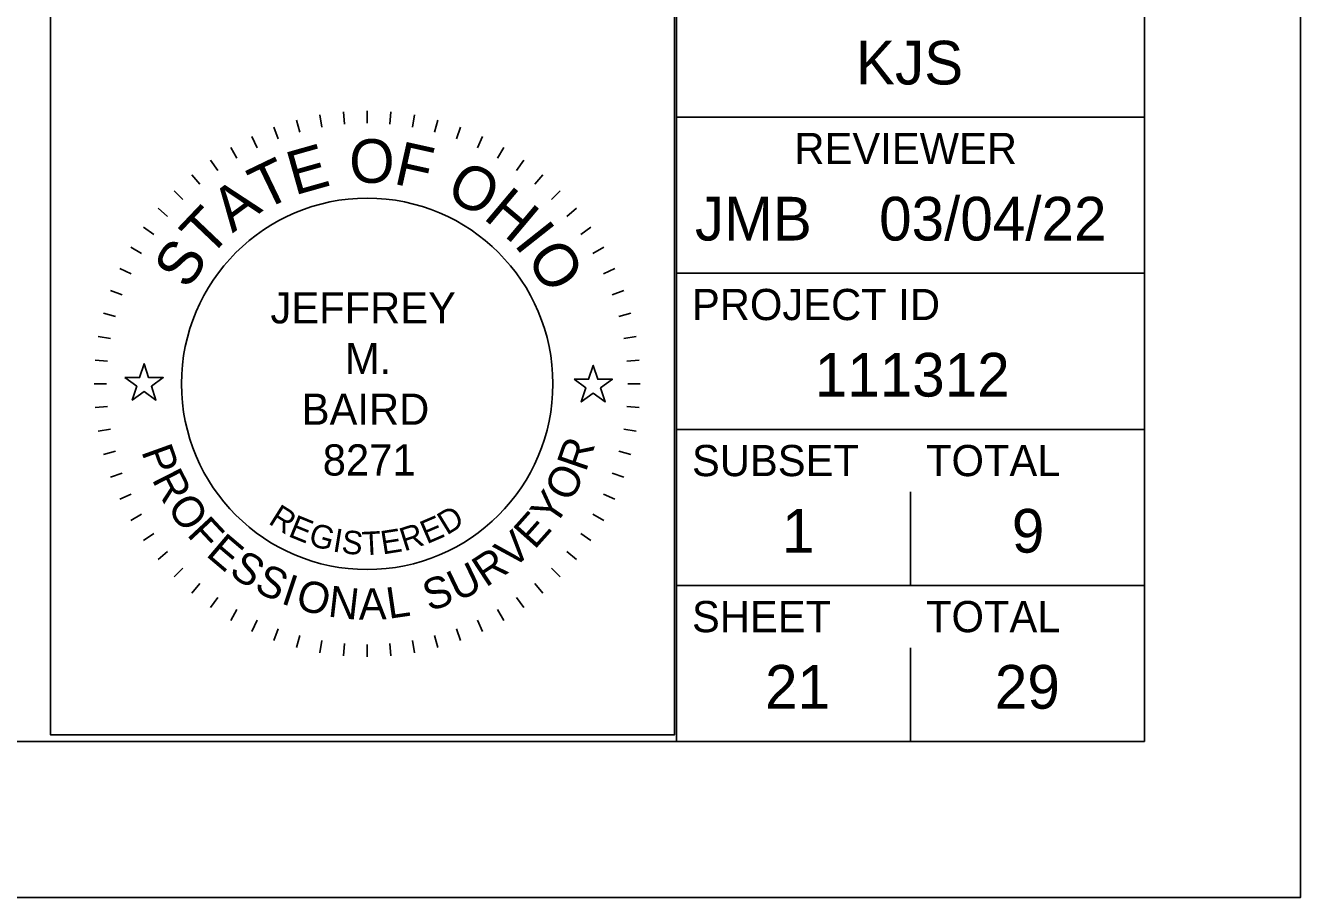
# Model space of a CAD drawing. Extents: x 0 to 104, y 0 to 37.
# Drawn here: x 29.914 to 34, y 0 to 2.794 of the extents above; entities that cross this region are included whole.
import ezdxf

# ---------------------------------------------------------------- set-up
doc = ezdxf.new("R2010")
doc.units = 0
for name, color, linetype in [('SC_Scratch3', 7, 'Continuous'), ('SH_Cut_Line', 7, 'Continuous'), ('SH_Data', 7, 'Continuous'), ('SH_Named_Boundary', 7, 'Continuous')]:
    doc.layers.add(name, color=color, linetype=linetype)

msp = doc.modelspace()

# ---------------------------------------------------------------- linework, layer by layer
at = {"layer": 'SC_Scratch3'}
msp.add_lwpolyline([(0, 0), (34, 0), (34, 22), (0, 22)], close=True, dxfattribs=at)
at = {"layer": 'SH_Cut_Line'}
for p, q in [((30.8574, 2.5074), (30.8644, 2.468)), ((30.9331, 2.5174), (30.9366, 2.4776)), ((31.0094, 2.5207), (31.0094, 2.4807)), ((31.0856, 2.5174), (31.0822, 2.4776)), ((31.1613, 2.5074), (31.1544, 2.468)), ((30.7101, 2.468), (30.7238, 2.4304)), ((30.7829, 2.4909), (30.7933, 2.4523)), ((31.2358, 2.4909), (31.2255, 2.4523)), ((31.3086, 2.468), (31.295, 2.4304)), ((30.6396, 2.4388), (30.6565, 2.4025)), ((31.3792, 2.4388), (31.3623, 2.4025)), ((30.5719, 2.4035), (30.5919, 2.3689)), ((31.4469, 2.4035), (31.4269, 2.3689)), ((30.5075, 2.3625), (30.5304, 2.3297)), ((31.5113, 2.3625), (31.4883, 2.3297)), ((30.4469, 2.316), (30.4727, 2.2854)), ((31.5718, 2.316), (31.5461, 2.2854)), ((30.3907, 2.2645), (30.4189, 2.2362)), ((31.6281, 2.2645), (31.5998, 2.2362)), ((30.3391, 2.2082), (30.3697, 2.1825)), ((31.6797, 2.2082), (31.649, 2.1825)), ((30.2926, 2.1476), (30.3254, 2.1247)), ((31.7261, 2.1476), (31.6934, 2.1247)), ((30.2516, 2.0832), (30.2863, 2.0632)), ((31.7672, 2.0832), (31.7325, 2.0632)), ((30.2164, 2.0155), (30.2526, 1.9986)), ((31.8024, 2.0155), (31.7661, 1.9986)), ((30.1872, 1.945), (30.2247, 1.9313)), ((31.8316, 1.945), (31.794, 1.9313)), ((30.1642, 1.8722), (30.2028, 1.8618)), ((31.8546, 1.8722), (31.8159, 1.8618)), ((30.1477, 1.7977), (30.1871, 1.7907)), ((31.8711, 1.7977), (31.8317, 1.7907)), ((30.1377, 1.722), (30.1776, 1.7185)), ((31.8811, 1.722), (31.8412, 1.7185)), ((30.1344, 1.6457), (30.1744, 1.6457)), ((31.8844, 1.6457), (31.8444, 1.6457)), ((30.1377, 1.5695), (30.1776, 1.573)), ((31.8811, 1.5695), (31.8412, 1.573)), ((30.1477, 1.4938), (30.1871, 1.5007)), ((31.8711, 1.4938), (31.8317, 1.5007)), ((30.1642, 1.4193), (30.2028, 1.4296)), ((31.8546, 1.4193), (31.8159, 1.4296)), ((30.1872, 1.3465), (30.2247, 1.3601)), ((31.8316, 1.3465), (31.794, 1.3601)), ((30.2164, 1.2759), (30.2526, 1.2928)), ((31.8024, 1.2759), (31.7661, 1.2928)), ((32.75, 1), (32.75, 1.3)), ((30.2516, 1.2082), (30.2863, 1.2282)), ((31.7672, 1.2082), (31.7325, 1.2282)), ((30.2926, 1.1439), (30.3254, 1.1668)), ((31.7261, 1.1439), (31.6934, 1.1668)), ((30.3391, 1.0833), (30.3697, 1.109)), ((31.6797, 1.0833), (31.649, 1.109)), ((30.3907, 1.027), (30.4189, 1.0553)), ((31.6281, 1.027), (31.5998, 1.0553)), ((30.4469, 0.9754), (30.4727, 1.0061)), ((31.5718, 0.9754), (31.5461, 1.0061)), ((30.5075, 0.929), (30.5304, 0.9617)), ((31.5113, 0.929), (31.4883, 0.9617)), ((30.5719, 0.888), (30.5919, 0.9226)), ((31.4469, 0.888), (31.4269, 0.9226)), ((30.6396, 0.8527), (30.6565, 0.889)), ((30.7101, 0.8235), (30.7238, 0.8611)), ((31.3086, 0.8235), (31.295, 0.8611)), ((31.3792, 0.8527), (31.3623, 0.889)), ((30.7829, 0.8005), (30.7933, 0.8392)), ((30.8574, 0.784), (30.8644, 0.8234)), ((31.1613, 0.784), (31.1544, 0.8234)), ((31.2358, 0.8005), (31.2255, 0.8392)), ((30.9331, 0.7741), (30.9366, 0.8139)), ((31.0094, 0.7707), (31.0094, 0.8107)), ((31.0856, 0.7741), (31.0822, 0.8139)), ((32.75, 0.5), (32.75, 0.8)), ((32.375, 0.675), (32.375, 0.675))]:
    msp.add_line(p, q, dxfattribs=at)
for points in [[(30.233, 1.6657), (30.2799, 1.6657), (30.2944, 1.7103), (30.3089, 1.6657), (30.3558, 1.6657), (30.3179, 1.6381), (30.3324, 1.5935), (30.2944, 1.6211), (30.2564, 1.5935), (30.2709, 1.6381)], [(31.6721, 1.6603), (31.719, 1.6603), (31.7335, 1.7049), (31.748, 1.6603), (31.7949, 1.6603), (31.757, 1.6327), (31.7715, 1.5881), (31.7335, 1.6157), (31.6955, 1.5881), (31.71, 1.6327)]]:
    msp.add_lwpolyline(points, close=True, dxfattribs=at)
msp.add_circle((31.0094, 1.6457), 0.595, dxfattribs=at)
at = {"layer": 'SH_Data'}
msp.add_lwpolyline([(29.9944, 3.1213), (31.9944, 3.1213), (31.9944, 0.5213), (29.9944, 0.5213)], close=True, dxfattribs=at)
at = {"layer": 'SH_Named_Boundary'}
for p, q in [((32, 0.5), (32, 21.5)), ((32, 2.5), (33.5, 2.5)), ((32, 2), (33.5, 2)), ((32, 1.5), (33.5, 1.5)), ((32, 1), (33.5, 1))]:
    msp.add_line(p, q, dxfattribs=at)
msp.add_lwpolyline([(1.5, 21.5), (33.5, 21.5), (33.5, 0.5), (1.5, 0.5)], close=True, dxfattribs=at)

# ---------------------------------------------------------------- texts
at = {"layer": 'SH_Cut_Line'}
for s, height, p in [('KJS', 0.14, (32.5757, 2.605)), ('REVIEWER', 0.1, (32.3783, 2.35)), ('03/04/22', 0.14, (32.6497, 2.105)), ('JMB', 0.14, (32.0596, 2.105)), ('JEFFREY', 0.1, (30.6993, 1.8395)), ('PROJECT ID', 0.1, (32.05, 1.85)), ('M.', 0.1, (30.9379, 1.677)), ('111312', 0.14, (32.4435, 1.605)), ('BAIRD', 0.1, (30.7996, 1.5145)), ('8271', 0.1, (30.8669, 1.352)), ('SUBSET', 0.1, (32.05, 1.35)), ('TOTAL', 0.1, (32.8, 1.35)), ('1', 0.14, (32.3386, 1.105)), ('9', 0.14, (33.075, 1.105)), ('SHEET', 0.1, (32.05, 0.85)), ('TOTAL', 0.1, (32.8, 0.85)), ('21', 0.14, (32.2842, 0.605)), ('29', 0.14, (33.0206, 0.605))]:
    msp.add_text(s, height=height, dxfattribs=at).set_placement(p)
for s, height, rotation, p in [('E', 0.14, 15.7571, (30.7763, 2.2491)), ('O', 0.14, 359.7812, (30.9514, 2.29)), ('F', 0.14, 347.4362, (31.0905, 2.2875)), ('T', 0.14, 25.7167, (30.6755, 2.1997)), ('O', 0.14, 332.2586, (31.2556, 2.2439)), ('A', 0.14, 36.4747, (30.5779, 2.1276)), ('H', 0.14, 319.9136, (31.3778, 2.1774)), ('T', 0.14, 46.4344, (30.5011, 2.0458)), ('I', 0.14, 308.367, (31.4768, 2.0929)), ('S', 0.14, 57.1924, (30.4353, 1.9438)), ('O', 0.14, 303.1491, (31.5155, 2.0485)), ('P', 0.1, 289.7431, (30.2848, 1.4296)), ('R', 0.1, 70.983, (31.7097, 1.3606)), ('R', 0.1, 296.9802, (30.3178, 1.3401)), ('O', 0.1, 62.7428, (31.6616, 1.2632)), ('Y', 0.1, 55.5058, (31.6082, 1.1841)), ('O', 0.1, 304.7158, (30.3652, 1.2498)), ('R', 0.075, 327.8239, (30.6895, 1.1997)), ('D', 0.075, 31.466, (31.2644, 1.1594)), ('E', 0.1, 48.2687, (31.5453, 1.1123)), ('F', 0.1, 312.956, (30.4286, 1.1615)), ('E', 0.075, 337.7777, (30.7533, 1.1585)), ('G', 0.075, 344.2727, (30.8176, 1.1305)), ('R', 0.075, 17.6836, (31.1281, 1.1085)), ('E', 0.075, 23.3052, (31.2003, 1.1313)), ('E', 0.1, 319.6885, (30.4894, 1.0968)), ('I', 0.075, 350.6464, (30.8962, 1.1091)), ('S', 0.075, 353.7858, (30.9249, 1.1038)), ('T', 0.075, 3.0061, (30.9945, 1.0963)), ('E', 0.075, 8.9826, (31.0586, 1.0988)), ('V', 0.1, 41.0316, (31.4738, 1.049)), ('S', 0.1, 326.9255, (30.5627, 1.0356)), ('R', 0.1, 33.296, (31.3893, 0.992)), ('S', 0.1, 334.1626, (30.6431, 0.9842)), ('U', 0.1, 25.5604, (31.2978, 0.9468)), ('I', 0.1, 341.3997, (30.7294, 0.9434)), ('S', 0.1, 18.3234, (31.2075, 0.916)), ('O', 0.1, 345.1351, (30.7757, 0.9266)), ('N', 0.1, 353.3752, (30.8812, 0.9005)), ('A', 0.1, 1.1108, (30.9827, 0.8901)), ('L', 0.1, 8.3479, (31.0781, 0.8927))]:
    msp.add_text(s, height=height, rotation=rotation, dxfattribs=at).set_placement(p)

doc.saveas('drawing.dxf')
